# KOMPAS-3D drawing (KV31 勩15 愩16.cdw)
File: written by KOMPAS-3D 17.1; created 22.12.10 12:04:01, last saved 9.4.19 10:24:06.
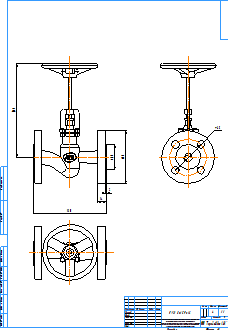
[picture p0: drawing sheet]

Title block, sheet 1: name: KV31 Ду15 Ру16; material: Внимание! Данный продукт является объектом авторского права ООО «Торговый Дом АДЛ». / Запрещается изменение, копирование, распространение / (в том числе путем копирования на другие сайты и ресурсы в Интернете) / или любое иное использование информации и объектов без предварительного / согласия правообладателя (ООО «Торговый Дом АДЛ»).; mass: 4; scale: 1:1; sheets: 1; organisation: ООО "Торговый дом АДЛ"; sheet format: A2; stored path: \\adlc.lan\data\АДЛ_ПКД\3D-модели\ADL production\Вентили ГРАНВЕНТ\KV31\KOMPAS 2D\KV31 Ду15.cdw

Views: Спереди 1, Проекционный вид 3, Вид 6
Dimensions and other numbers on the sheet: 46; 95; 65; 130; 2; 14; 167; 1:1; 1; 4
